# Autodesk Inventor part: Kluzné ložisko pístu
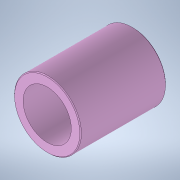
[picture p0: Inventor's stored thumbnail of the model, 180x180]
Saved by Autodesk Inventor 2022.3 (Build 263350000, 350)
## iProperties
Created: 2025-11
Part Number: Kluzné ložisko pístu
Material: Všeobecné
Document SubType Name: Modeling
Designer: Hra42
Density: 1 g/cm^3
Appearance: Výchozí
Sending System: SolidWorks 2012
Last Author: Hra42
Last Saved: 2025-11-14
Author: Hra42
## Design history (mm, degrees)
feature "T_X2_011B_X0_leso1"
chamfer "Zkosení1" distance "d0" = 0.3; stored, may be unused: second distance "d1" = 2, angle "d2" = 45 deg
node "Těleso1"
